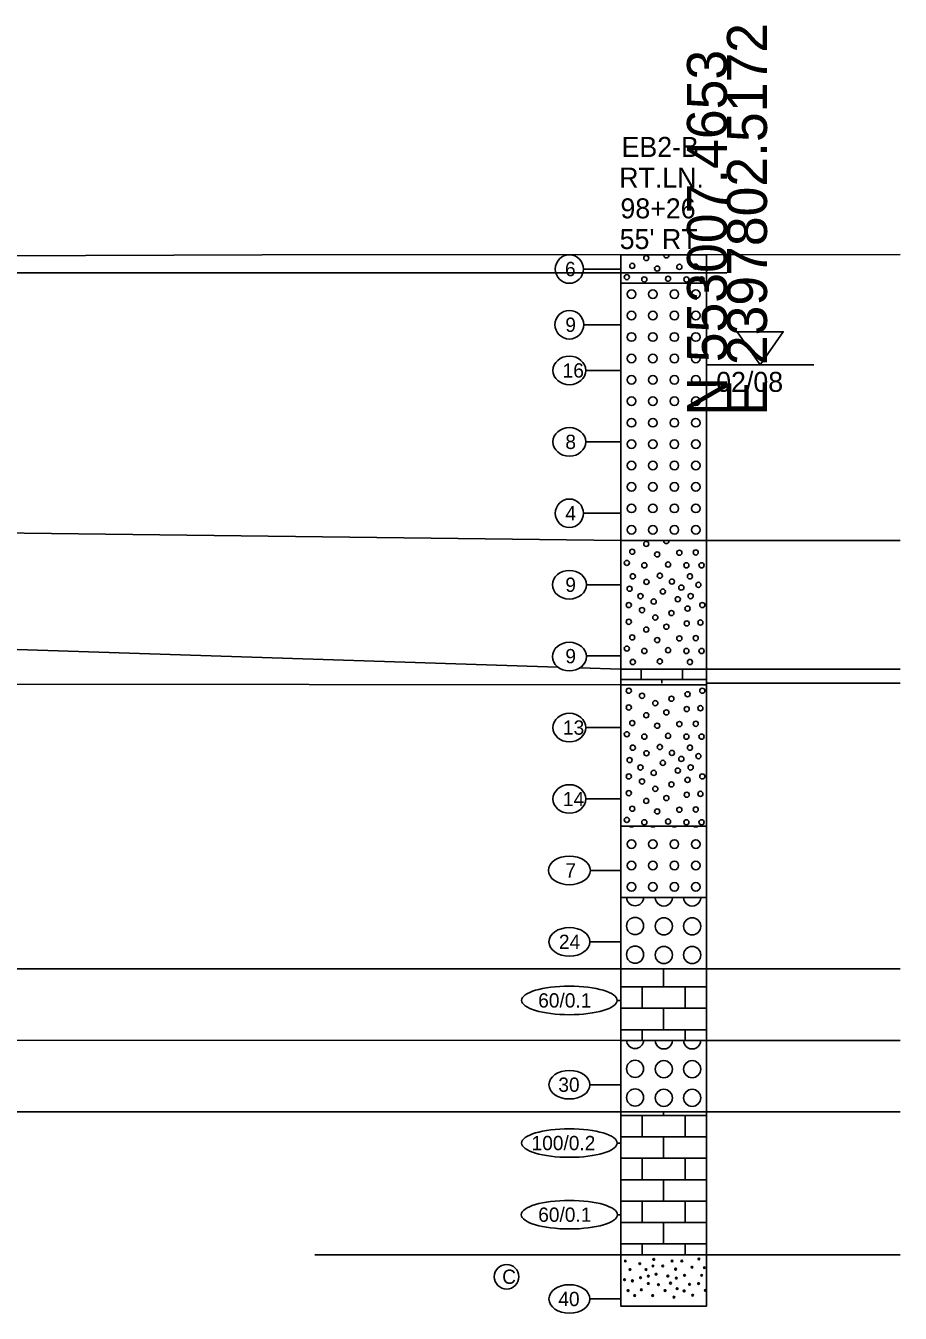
# Model space of a CAD drawing. Extents: x -26 to 164, y -74 to 517.
# Drawn here: x 96.7 to 157.9, y 427.2 to 517.3 of the extents above; entities that cross this region are included whole.
import ezdxf

# ---------------------------------------------------------------- set-up
doc = ezdxf.new("R2010")
doc.units = 0
for name, color, linetype in [('Default', 7, 'Continuous'), ('Exist XS Ground Line', 7, 'Continuous'), ('Old_Level_63', 7, 'Continuous'), ('Prop Road Sect_ Boring - Header Labels from Geopak', 7, 'Continuous'), ('Prop Road Sect_ Boring - Material (Outline)', 7, 'Continuous'), ('Prop Road Sect_ Boring - Peripheral (24 Hr GrdWtr Date)', 7, 'Continuous'), ('Prop Road Sect_ Boring - Peripheral (SPT Oval + Leader)', 7, 'Continuous'), ('Prop Road Sect_ Boring - Peripheral (SPT Tx)', 7, 'Continuous'), ('Prop Road Sect_ Material - Contact (General - Minor)', 7, 'Continuous'), ('Prop Road Sect_ Material - Tx (Composite Desc)', 7, 'Continuous'), ('Water Mark (24 Hr) Cell', 7, 'Continuous')]:
    doc.layers.add(name, color=color, linetype=linetype)

msp = doc.modelspace()

# ---------------------------------------------------------------- linework, layer by layer
at = {"layer": 'Default'}
for p, q in [((141.32, 450.012), (141.32, 451.266)), ((138.326, 450.012), (144.32, 450.012)), ((139.82, 448.514), (139.82, 450.012)), ((142.82, 448.514), (142.82, 450.012)), ((144.323, 450.012), (144.326, 450.012)), ((138.326, 448.514), (144.32, 448.514)), ((141.32, 447.015), (141.32, 448.514)), ((144.323, 448.514), (144.326, 448.514)), ((138.326, 447.015), (144.32, 447.015)), ((139.82, 446.266), (139.82, 447.015)), ((142.82, 446.266), (142.82, 447.015)), ((144.323, 447.015), (144.326, 447.015)), ((138.326, 441.009), (144.32, 441.009)), ((139.82, 439.511), (139.82, 441.009)), ((141.32, 441.009), (141.32, 441.266)), ((142.82, 439.511), (142.82, 441.009)), ((144.323, 441.009), (144.326, 441.009)), ((138.326, 439.511), (144.32, 439.511)), ((141.32, 438.012), (141.32, 439.511)), ((144.323, 439.511), (144.326, 439.511)), ((138.326, 438.012), (144.32, 438.012)), ((139.82, 437.263), (139.82, 438.012)), ((139.82, 436.511), (139.82, 437.26)), ((142.82, 437.263), (142.82, 438.012)), ((142.82, 436.511), (142.82, 437.26)), ((144.323, 438.012), (144.326, 438.012)), ((138.326, 436.511), (144.32, 436.511)), ((141.32, 435.012), (141.32, 436.511)), ((144.323, 436.511), (144.326, 436.511)), ((138.326, 435.012), (144.32, 435.012)), ((139.82, 433.514), (139.82, 435.012)), ((142.82, 433.514), (142.82, 435.012)), ((144.323, 435.012), (144.326, 435.012)), ((138.326, 433.514), (144.32, 433.514)), ((141.32, 432.015), (141.32, 433.514)), ((144.323, 433.514), (144.326, 433.514)), ((138.326, 432.015), (144.32, 432.015)), ((139.82, 431.266), (139.82, 432.015)), ((142.82, 431.266), (142.82, 432.015)), ((144.323, 432.015), (144.326, 432.015))]:
    msp.add_line(p, q, dxfattribs=at)
for centre, radius in [((139.073, 498.505), 0.3), ((140.573, 498.505), 0.3), ((142.073, 498.505), 0.3), ((143.573, 498.505), 0.3), ((139.073, 497.005), 0.3), ((140.573, 497.005), 0.3), ((142.073, 497.005), 0.3), ((143.573, 497.005), 0.3), ((139.073, 495.505), 0.3), ((140.573, 495.505), 0.3), ((142.073, 495.505), 0.3), ((143.573, 495.505), 0.3), ((139.073, 494.005), 0.3), ((140.573, 494.005), 0.3), ((142.073, 494.005), 0.3), ((143.573, 494.005), 0.3), ((139.073, 492.508), 0.3), ((140.573, 492.508), 0.3), ((142.073, 492.508), 0.3), ((143.573, 492.508), 0.3), ((139.073, 491.008), 0.3), ((140.573, 491.008), 0.3), ((142.073, 491.008), 0.3), ((143.573, 491.008), 0.3), ((139.073, 489.508), 0.3), ((140.573, 489.508), 0.3), ((142.073, 489.508), 0.3), ((143.573, 489.508), 0.3), ((139.073, 488.008), 0.3), ((140.573, 488.008), 0.3), ((142.073, 488.008), 0.3), ((143.573, 488.008), 0.3), ((139.073, 486.511), 0.3), ((140.573, 486.511), 0.3), ((142.073, 486.511), 0.3), ((143.573, 486.511), 0.3), ((139.073, 485.011), 0.3), ((140.573, 485.011), 0.3), ((142.073, 485.011), 0.3), ((143.573, 485.011), 0.3), ((139.073, 483.511), 0.3), ((140.573, 483.511), 0.3), ((142.073, 483.511), 0.3), ((143.573, 483.511), 0.3), ((139.073, 482.011), 0.3), ((140.573, 482.011), 0.3), ((142.073, 482.011), 0.3), ((143.573, 482.011), 0.3), ((139.128, 480.476), 0.18), ((140.109, 481.022), 0.18), ((140.871, 480.287), 0.18), ((142.422, 480.407), 0.18), ((143.568, 480.425), 0.18), ((138.747, 479.69), 0.18), ((139.971, 479.525), 0.18), ((141.633, 479.579), 0.18), ((142.914, 479.525), 0.18), ((143.976, 479.525), 0.18), ((139.165, 478.752), 0.18), ((141.056, 478.799), 0.18), ((143.165, 478.752), 0.18), ((138.939, 477.884), 0.18), ((140.121, 478.362), 0.18), ((141.266, 477.688), 0.18), ((141.903, 478.384), 0.18), ((142.56, 477.965), 0.18), ((143.757, 478.157), 0.18), ((138.885, 476.741), 0.18), ((139.701, 477.368), 0.18), ((140.625, 476.987), 0.18), ((142.314, 477.149), 0.18), ((143.214, 477.368), 0.18), ((144.03, 476.741), 0.18), ((139.809, 476.387), 0.18), ((140.739, 475.871), 0.18), ((141.867, 476.18), 0.18), ((142.995, 476.495), 0.18), ((138.885, 475.571), 0.18), ((140.109, 475.025), 0.18), ((141.513, 475.223), 0.18), ((142.941, 475.46), 0.18), ((143.895, 475.517), 0.18), ((139.128, 474.479), 0.18), ((140.871, 474.29), 0.18), ((142.422, 474.41), 0.18), ((143.568, 474.428), 0.18), ((138.747, 473.693), 0.18), ((139.971, 473.528), 0.18), ((141.633, 473.582), 0.18), ((142.914, 473.528), 0.18), ((143.976, 473.528), 0.18), ((139.165, 472.755), 0.18), ((141.056, 472.802), 0.18), ((143.165, 472.755), 0.18), ((138.885, 470.744), 0.18), ((139.809, 470.39), 0.18), ((142.995, 470.498), 0.18), ((144.03, 470.744), 0.18), ((138.885, 469.574), 0.18), ((140.739, 469.874), 0.18), ((141.867, 470.183), 0.18), ((142.941, 469.463), 0.18), ((143.895, 469.52), 0.18), ((140.109, 469.028), 0.18), ((141.513, 469.226), 0.18), ((138.747, 467.696), 0.18), ((139.128, 468.482), 0.18), ((140.871, 468.293), 0.18), ((142.422, 468.413), 0.18), ((143.568, 468.431), 0.18), ((139.165, 466.758), 0.18), ((139.971, 467.531), 0.18), ((141.056, 466.805), 0.18), ((141.633, 467.585), 0.18), ((142.914, 467.531), 0.18), ((143.165, 466.758), 0.18), ((143.976, 467.531), 0.18), ((138.939, 465.89), 0.18), ((140.121, 466.368), 0.18), ((141.903, 466.39), 0.18), ((142.56, 465.971), 0.18), ((143.757, 466.163), 0.18), ((139.701, 465.374), 0.18), ((140.625, 464.993), 0.18), ((141.266, 465.694), 0.18), ((142.314, 465.155), 0.18), ((143.214, 465.374), 0.18), ((138.885, 464.747), 0.18), ((139.809, 464.393), 0.18), ((141.867, 464.186), 0.18), ((142.995, 464.501), 0.18), ((144.03, 464.747), 0.18), ((138.885, 463.577), 0.18), ((140.739, 463.877), 0.18), ((141.513, 463.229), 0.18), ((142.941, 463.466), 0.18), ((143.895, 463.523), 0.18), ((139.128, 462.485), 0.18), ((140.109, 463.031), 0.18), ((140.871, 462.296), 0.18), ((142.422, 462.416), 0.18), ((143.568, 462.434), 0.18), ((138.747, 461.699), 0.18), ((139.971, 461.534), 0.18), ((141.633, 461.588), 0.18), ((142.914, 461.534), 0.18), ((143.976, 461.534), 0.18), ((139.073, 460.011), 0.3), ((140.573, 460.011), 0.3), ((142.073, 460.011), 0.3), ((143.573, 460.011), 0.3), ((139.073, 458.511), 0.3), ((140.573, 458.511), 0.3), ((142.073, 458.511), 0.3), ((143.573, 458.511), 0.3), ((139.073, 457.011), 0.3), ((140.573, 457.011), 0.3), ((142.073, 457.011), 0.3), ((143.573, 457.011), 0.3), ((139.324, 454.279), 0.6), ((141.334, 454.255), 0.6), ((143.32, 454.255), 0.6), ((139.324, 452.269), 0.6), ((141.334, 452.245), 0.6), ((143.32, 452.245), 0.6), ((139.324, 444.279), 0.6), ((141.334, 444.255), 0.6), ((143.32, 444.255), 0.6), ((139.324, 442.269), 0.6), ((141.334, 442.245), 0.6), ((143.32, 442.245), 0.6)]:
    msp.add_circle(centre, radius, dxfattribs=at)
for centre, radius, start, end in [((141.513, 481.22), 0.18, 165.28168, 14.71832), ((139.073, 461.511), 0.3, 234.86296, 305.13704), ((140.573, 461.511), 0.3, 234.86296, 305.13704), ((142.073, 461.511), 0.3, 234.86296, 305.13704), ((143.573, 461.511), 0.3, 234.86296, 305.13704), ((139.324, 456.295), 0.6, 182.75672, 357.24328), ((141.334, 456.265), 0.6, 179.89087, 0.10913), ((143.32, 456.265), 0.6, 179.89087, 0.10913), ((139.324, 446.295), 0.6, 182.75672, 357.24328), ((141.334, 446.265), 0.6, 179.89087, 0.10913), ((143.32, 446.265), 0.6, 179.89087, 0.10913)]:
    msp.add_arc(centre, radius, start, end, dxfattribs=at)
at = {"layer": 'Exist XS Ground Line'}
msp.add_lwpolyline([(-13.067, 501.317), (33.207, 501.249), (58.756, 501.152), (69.47, 501.144), (71.172, 501.093), (73.278, 501.13), (73.954, 501.128), (76.756, 501.135), (88.476, 501.162), (113.218, 501.254), (157.868, 501.284)], dxfattribs=at)
at = {"layer": 'Old_Level_63'}
msp.add_line((76.756, 500), (145.757, 500), dxfattribs=at)
at = {"layer": 'Prop Road Sect_ Boring - Material (Outline)'}
for p, q in [((138.327, 472.26), (144.314, 472.26)), ((138.326, 471.164), (144.313, 471.164))]:
    msp.add_line(p, q, dxfattribs=at)
for points in [[(138.326, 501.266), (144.326, 501.266), (144.326, 499.266), (138.326, 499.266)], [(138.326, 499.266), (144.326, 499.266), (144.326, 481.266), (138.326, 481.266)], [(138.326, 481.266), (144.326, 481.266), (144.326, 461.266), (138.326, 461.266)], [(138.326, 461.266), (144.326, 461.266), (144.326, 456.266), (138.326, 456.266)], [(138.326, 456.266), (144.326, 456.266), (144.326, 451.266), (138.326, 451.266)], [(138.326, 451.266), (144.326, 451.266), (144.326, 446.266), (138.326, 446.266)], [(138.326, 446.266), (144.326, 446.266), (144.326, 441.266), (138.326, 441.266)], [(138.326, 441.266), (144.326, 441.266), (144.326, 431.266), (138.326, 431.266)], [(138.326, 431.266), (144.326, 431.266), (144.326, 427.67), (138.326, 427.67)]]:
    msp.add_lwpolyline(points, close=True, dxfattribs=at)
for centre, radius in [((140.109, 501.031), 0.18), ((139.128, 500.485), 0.18), ((140.871, 500.296), 0.18), ((142.422, 500.416), 0.18), ((143.568, 500.434), 0.18), ((138.747, 499.699), 0.18), ((139.971, 499.534), 0.18), ((141.633, 499.588), 0.18), ((142.914, 499.534), 0.18), ((143.976, 499.534), 0.18), ((138.645, 430.826), 0.06), ((140.634, 430.934), 0.06), ((141.915, 430.826), 0.06), ((142.596, 430.826), 0.06), ((143.793, 430.961), 0.06), ((138.972, 430.226), 0.06), ((139.653, 430.634), 0.06), ((140.088, 430.226), 0.06), ((140.58, 430.472), 0.06), ((140.796, 429.899), 0.06), ((141.261, 430.472), 0.06), ((142.158, 430.253), 0.06), ((143.304, 430.388), 0.06), ((144.174, 430.361), 0.06), ((138.591, 429.518), 0.06), ((139.137, 429.437), 0.06), ((139.707, 429.653), 0.06), ((140.253, 429.764), 0.06), ((140.253, 429.245), 0.06), ((140.961, 429.164), 0.06), ((141.615, 429.764), 0.06), ((141.804, 429.272), 0.06), ((142.212, 429.626), 0.06), ((142.785, 429.818), 0.06), ((143.139, 429.191), 0.06), ((143.766, 429.245), 0.06), ((143.985, 429.818), 0.06), ((138.837, 428.756), 0.06), ((139.299, 428.402), 0.06), ((139.764, 428.81), 0.06), ((140.553, 428.402), 0.06), ((141.423, 428.756), 0.06), ((142.05, 428.291), 0.06), ((142.269, 428.891), 0.06), ((142.758, 428.729), 0.06), ((143.358, 428.429), 0.06), ((144.25, 428.766), 0.06)]:
    msp.add_circle(centre, radius, dxfattribs=at)
msp.add_arc((141.513, 501.229), 0.18, 168.2251, 11.7749, dxfattribs=at)
at = {"layer": 'Prop Road Sect_ Boring - Peripheral (SPT Oval + Leader)'}
for p, q in [((138.326, 500.266), (135.709, 500.266)), ((138.326, 496.366), (135.733, 496.366)), ((138.326, 493.166), (135.875, 493.166)), ((138.326, 488.166), (135.875, 488.166)), ((138.326, 483.166), (135.709, 483.166)), ((138.326, 478.166), (135.914, 478.166)), ((138.326, 473.188), (135.914, 473.188)), ((138.327, 471.539), (144.071, 471.539)), ((139.758, 471.539), (139.758, 472.257)), ((141.196, 471.266), (141.196, 471.539)), ((142.633, 471.539), (142.633, 472.257)), ((144.074, 471.539), (144.323, 471.539)), ((138.326, 468.166), (135.875, 468.166)), ((138.326, 463.166), (135.875, 463.166)), ((138.326, 458.166), (136.198, 458.166)), ((138.326, 453.166), (136.158, 453.166)), ((138.326, 449.066), (138.072, 449.066)), ((138.326, 443.166), (136.158, 443.166)), ((138.326, 439.082), (138.072, 439.082)), ((138.326, 434.066), (138.095, 434.066)), ((138.326, 428.166), (136.158, 428.166))]:
    msp.add_line(p, q, dxfattribs=at)
for centre, major_axis, ratio in [((134.726, 500.266), (0, 1), 0.983465), ((134.726, 496.366), (1.007, 0), 0.992963), ((134.726, 493.166), (1.149, 0), 0.870459), ((134.726, 488.166), (1.149, 0), 0.870459), ((134.726, 483.166), (0, 1), 0.983465), ((134.726, 478.166), (1.188, 0), 0.841617), ((134.726, 473.134), (1.188, 0), 0.841617), ((134.726, 468.166), (1.149, 0), 0.870459), ((134.726, 463.166), (1.149, 0), 0.870459), ((134.726, 458.166), (1.472, 0), 0.679508), ((134.726, 453.166), (1.432, 0), 0.698186), ((134.726, 449.066), (3.346, 0), 0.298894), ((134.726, 443.166), (1.432, 0), 0.698186), ((134.726, 439.082), (3.346, 0), 0.298894), ((134.726, 434.066), (3.369, 0), 0.296798), ((134.726, 428.166), (1.432, 0), 0.698186)]:
    msp.add_ellipse(centre, major_axis=major_axis, ratio=ratio, dxfattribs=at)
at = {"layer": 'Prop Road Sect_ Material - Contact (General - Minor)'}
for p, q in [((14.656, 482.781), (138.326, 481.266)), ((144.326, 481.266), (157.882, 481.266)), ((14.656, 476.281), (133.914, 472.404)), ((135.469, 472.353), (138.327, 472.26)), ((144.314, 472.26), (157.869, 472.26)), ((14.656, 471.281), (138.326, 471.164)), ((144.326, 471.266), (157.882, 471.266)), ((138.326, 451.266), (14.656, 451.281)), ((144.326, 451.266), (157.882, 451.266)), ((14.656, 446.281), (138.326, 446.266)), ((144.326, 446.266), (157.882, 446.266)), ((14.656, 441.281), (138.326, 441.266)), ((144.326, 441.266), (157.882, 441.266)), ((138.326, 431.266), (116.918, 431.266)), ((144.326, 431.266), (157.882, 431.266))]:
    msp.add_line(p, q, dxfattribs=at)
at = {"layer": 'Prop Road Sect_ Material - Tx (Composite Desc)'}
msp.add_circle((130.329, 429.723), 0.86, dxfattribs=at)
at = {"layer": 'Water Mark (24 Hr) Cell'}
for p, q in [((144.326, 493.566), (148.076, 493.566)), ((148.076, 493.566), (151.826, 493.566))]:
    msp.add_line(p, q, dxfattribs=at)
msp.add_lwpolyline([(146.464, 495.872), (149.689, 495.872), (148.076, 493.566)], close=True, dxfattribs=at)

# ---------------------------------------------------------------- texts
at = {"layer": 'Old_Level_63'}
for s, p in [('E 2397802.5172', (148.557, 490)), ('N 553007.4653', (145.757, 490))]:
    msp.add_text(s, height=2.8, rotation=90, dxfattribs=at).set_placement(p)
at = {"layer": 'Prop Road Sect_ Boring - Header Labels from Geopak'}
for s, p in [('EB2-B', (138.377, 508.113)), ('RT.LN.', (138.212, 505.963)), ('98+26', (138.3, 503.813)), ("55' RT", (138.245, 501.663))]:
    msp.add_text(s, height=1.4, dxfattribs=at).set_placement(p)
at = {"layer": 'Prop Road Sect_ Boring - Peripheral (24 Hr GrdWtr Date)'}
msp.add_text('02/08', height=1.4, dxfattribs=at).set_placement((145, 491.666))
at = {"layer": 'Prop Road Sect_ Boring - Peripheral (SPT Tx)'}
for s, p in [('6', (134.419, 499.766)), ('9', (134.443, 495.866)), ('16', (134.254, 492.666)), ('8', (134.443, 487.666)), ('4', (134.443, 482.666)), ('9', (134.443, 477.666)), ('9', (134.443, 472.666)), ('13', (134.277, 467.666)), ('14', (134.277, 462.666)), ('7', (134.443, 457.666)), ('24', (133.994, 452.666)), ('60/0.1', (132.545, 448.566)), ('30', (133.954, 442.666)), ('100/0.2', (132.08, 438.582)), ('60/0.1', (132.545, 433.566)), ('40', (133.954, 427.666))]:
    msp.add_text(s, height=1, dxfattribs=at).set_placement(p)
at = {"layer": 'Prop Road Sect_ Material - Tx (Composite Desc)'}
msp.add_text('C', height=1, dxfattribs=at).set_placement((130.022, 429.223))

doc.saveas('drawing.dxf')
